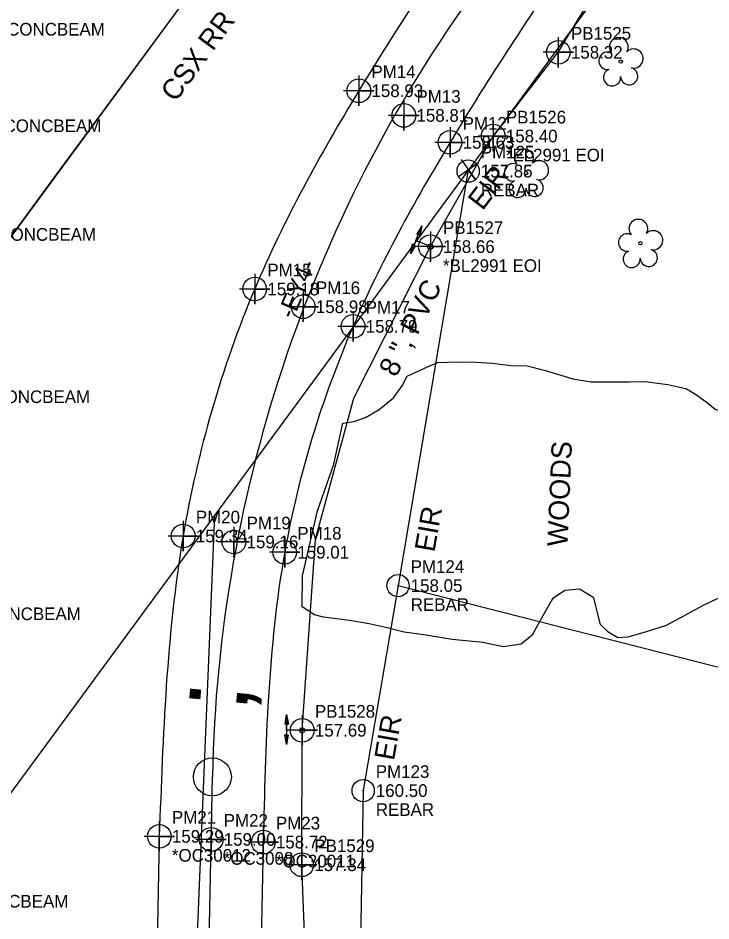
# Model space of a CAD drawing. Extents: x 2262665 to 2270527, y 505476 to 514960.
# Drawn here: x 2266364.6 to 2266501.5, y 510510.2 to 510688.6 of the extents above; entities that cross this region are included whole.
import ezdxf

# ---------------------------------------------------------------- set-up
doc = ezdxf.new("R2010")
doc.units = 0
for name, color, linetype in [('Default Symbol Cogo Comment', 7, 'Continuous'), ('Default Symbol Cogo Elevation', 7, 'Continuous'), ('Default Symbol Cogo Number', 7, 'Continuous'), ('Exist DTM Crownline Cogo Comment', 7, 'Continuous'), ('Exist DTM Crownline Cogo Elevation', 7, 'Continuous'), ('Exist DTM Crownline Cogo Number', 7, 'Continuous'), ('Exist DTM Crownline Cogo Point CELL', 7, 'Continuous'), ('Exist Horizontal Alignment', 7, 'Continuous'), ('Exist Horizontal Alignment Direction Label', 7, 'Continuous'), ('Exist Property Corner CELL', 7, 'Continuous'), ('Exist Property Iron Pin CELL', 7, 'Continuous'), ('Exist Property Iron Pin Cogo Comment', 7, 'Continuous'), ('Exist Property Iron Pin Cogo Elevation', 7, 'Continuous'), ('Exist Property Iron Pin Cogo Number', 7, 'Continuous'), ('Exist Property Iron Pin Text', 7, 'Continuous'), ('Exist Property Line', 7, 'Continuous'), ('Exist Railroads Standard Gauge', 7, 'Continuous'), ('Exist Railroads Standard Gauge Text', 7, 'Continuous'), ('Exist Right of Way Line', 7, 'Continuous'), ('Exist Roads EOP', 7, 'Continuous'), ('Exist Roads EOP Cogo Comment', 7, 'Continuous'), ('Exist Roads EOP Cogo Elevation', 7, 'Continuous'), ('Exist Roads EOP Cogo Number', 7, 'Continuous'), ('Exist Roads EOP Cogo Point CELL', 7, 'Continuous'), ('Exist Utilities Water Change of Service SUE CELL', 7, 'Continuous'), ('Exist Utilities Water UG Line SUE LOS B', 7, 'Continuous'), ('Exist Utilities Water UG Line SUE LOS B Cogo Comment', 7, 'Continuous'), ('Exist Utilities Water UG Line SUE LOS B Cogo Elevation', 7, 'Continuous'), ('Exist Utilities Water UG Line SUE LOS B Cogo Number', 7, 'Continuous'), ('Exist Utilities Water UG Line SUE LOS B Cogo Point CELL', 7, 'Continuous'), ('Exist Utilities Water UG Line SUE LOS B Text', 7, 'Continuous'), ('Exist Utilities Water UG Line SUE LOS C', 7, 'Continuous'), ('Exist Vegetation Tree CELL', 7, 'Continuous'), ('Exist Vegetation Woods Line', 7, 'Continuous'), ('Exist Vegetation Woods Line Text', 7, 'Continuous'), ('Scratch_Level_1', 7, 'Continuous')]:
    doc.layers.add(name, color=color, linetype=linetype)

msp = doc.modelspace()

# ---------------------------------------------------------------- linework, layer by layer
at = {"layer": 'Exist DTM Crownline Cogo Point CELL'}
for points in [[(2266440.82, 510672.39), (2266440.82, 510666.39), (2266440.82, 510669.39), (2266443.82, 510669.39), (2266437.82, 510669.39)], [(2266420.94, 510634.58), (2266420.94, 510628.58), (2266420.94, 510631.58), (2266423.94, 510631.58), (2266417.94, 510631.58)], [(2266407.24, 510588.1), (2266407.24, 510582.1), (2266407.24, 510585.1), (2266410.24, 510585.1), (2266404.24, 510585.1)], [(2266402.73, 510529.32), (2266402.73, 510523.32), (2266402.73, 510526.32), (2266405.73, 510526.32), (2266399.73, 510526.32)]]:
    msp.add_lwpolyline(points, dxfattribs=at)
for centre in [(2266440.82, 510669.39), (2266420.94, 510631.58), (2266407.24, 510585.1), (2266402.73, 510526.32)]:
    msp.add_circle(centre, 2.34, dxfattribs=at)
at = {"layer": 'Exist Horizontal Alignment'}
for p, q in [((2266115.37, 510308.34), (2266484.61, 510810.55)), ((2266397.92, 510285.5), (2266402.98, 510538.68))]:
    msp.add_line(p, q, dxfattribs=at)
msp.add_circle((2266402.98, 510538.68), 3.75, dxfattribs=at)
msp.add_arc((2266677.92, 510533.19), 275, 143.4649, 178.8564, dxfattribs=at)
at = {"layer": 'Exist Property Corner CELL'}
msp.add_line((2266453.57, 510658.61), (2266453.57, 510658.61), dxfattribs=at)
msp.add_lwpolyline([(2266452.13, 510660.65), (2266455.02, 510656.57), (2266453.57, 510658.61), (2266455.61, 510660.06), (2266451.54, 510657.16)], dxfattribs=at)
at = {"layer": 'Exist Property Iron Pin CELL'}
for centre, radius in [((2266453.54, 510658.38), 2.2), ((2266453.54, 510658.38), 0.0707), ((2266439.68, 510576.48), 2.2), ((2266439.68, 510576.48), 0.0707), ((2266432.78, 510535.97), 2.2), ((2266432.78, 510535.97), 0.0707)]:
    msp.add_circle(centre, radius, dxfattribs=at)
at = {"layer": 'Exist Property Line'}
msp.add_line((2266439.68, 510576.48), (2266650.69, 510522.69), dxfattribs=at)
at = {"layer": 'Exist Railroads Standard Gauge'}
msp.add_lwpolyline([(2266050.13, 510219.7), (2266084.79, 510266.49), (2266115.4, 510308.45), (2266145.35, 510349.15), (2266177.14, 510392.25), (2266205.29, 510430.68), (2266238.56, 510475.95), (2266285.01, 510539.01), (2266316.09, 510581.21), (2266370.93, 510656.02), (2266407.4, 510705.52), (2266453.51, 510768.36), (2266484.6, 510810.49), (2266484.6, 510810.49), (2266581.19, 510941.59), (2266616.47, 510989.01)], dxfattribs=at)
at = {"layer": 'Exist Right of Way Line'}
for p, q in [((2266927.92, 511303.77), (2265541.79, 509418.49)), ((2266453.57, 510658.61), (2266439.68, 510576.48)), ((2266439.68, 510576.48), (2266432.78, 510535.97)), ((2266432.78, 510535.97), (2266427.23, 510222.84))]:
    msp.add_line(p, q, dxfattribs=at)
at = {"layer": 'Exist Roads EOP'}
for points in [[(2266392.49, 510526.92), (2266390.63, 510426.97), (2266389.2, 510321.43), (2266387.02, 510213.77)], [(2266413.04, 510525.79), (2266411.05, 510426.91), (2266409.59, 510321.14), (2266405.94, 510212.74)]]:
    msp.add_lwpolyline(points, dxfattribs=at)
for points in [[(2266484.46, 510750.28), (2266457.74, 510713.54), (2266431.92, 510674.26), (2266411.35, 510635.08), (2266397.21, 510586.27), (2266392.49, 510526.92)], [(2266500.79, 510738.24), (2266474.62, 510701.96), (2266449.95, 510664.06), (2266430.79, 510627.7), (2266417.27, 510583.06), (2266413.04, 510525.79)]]:
    msp.add_spline(points, degree=3, dxfattribs=at)
at = {"layer": 'Exist Roads EOP Cogo Point CELL'}
for points in [[(2266431.92, 510677.26), (2266431.92, 510671.26), (2266431.92, 510674.26), (2266434.92, 510674.26), (2266428.92, 510674.26)], [(2266449.95, 510667.06), (2266449.95, 510661.06), (2266449.95, 510664.06), (2266452.95, 510664.06), (2266446.95, 510664.06)], [(2266411.35, 510638.08), (2266411.35, 510632.08), (2266411.35, 510635.08), (2266414.35, 510635.08), (2266408.35, 510635.08)], [(2266430.79, 510630.7), (2266430.79, 510624.7), (2266430.79, 510627.7), (2266433.79, 510627.7), (2266427.79, 510627.7)], [(2266397.21, 510589.27), (2266397.21, 510583.27), (2266397.21, 510586.27), (2266400.21, 510586.27), (2266394.21, 510586.27)], [(2266417.27, 510586.06), (2266417.27, 510580.06), (2266417.27, 510583.06), (2266420.27, 510583.06), (2266414.27, 510583.06)], [(2266392.49, 510529.92), (2266392.49, 510523.92), (2266392.49, 510526.92), (2266395.49, 510526.92), (2266389.49, 510526.92)], [(2266413.04, 510528.79), (2266413.04, 510522.79), (2266413.04, 510525.79), (2266416.04, 510525.79), (2266410.04, 510525.79)]]:
    msp.add_lwpolyline(points, dxfattribs=at)
for centre in [(2266431.92, 510674.26), (2266449.95, 510664.06), (2266411.35, 510635.08), (2266430.79, 510627.7), (2266397.21, 510586.27), (2266417.27, 510583.06), (2266392.49, 510526.92), (2266413.04, 510525.79)]:
    msp.add_circle(centre, 2.34, dxfattribs=at)
at = {"layer": 'Exist Utilities Water Change of Service SUE CELL'}
for p, q in [((2266444.41, 510647.54), (2266442.13, 510642.03)), ((2266443.21, 510644.64), (2266444.41, 510647.54)), ((2266446.06, 510643.46), (2266443.21, 510644.64)), ((2266446.06, 510643.46), (2266446.06, 510643.46)), ((2266417.65, 510547.88), (2266417.65, 510551.01)), ((2266417.65, 510551.01), (2266417.65, 510545.05)), ((2266420.74, 510547.88), (2266417.65, 510547.88)), ((2266420.74, 510547.88), (2266420.74, 510547.88))]:
    msp.add_line(p, q, dxfattribs=at)
for points in [[(2266444.41, 510647.54), (2266443.97, 510645.58), (2266443.81, 510646.1), (2266443.39, 510645.87)], [(2266442.13, 510642.03), (2266442.56, 510643.98), (2266442.72, 510643.46), (2266443.15, 510643.69)], [(2266417.65, 510551.01), (2266418, 510549.04), (2266417.65, 510549.46), (2266417.35, 510549.08)], [(2266417.65, 510545.05), (2266417.31, 510547.02), (2266417.65, 510546.6), (2266417.96, 510546.98)]]:
    msp.add_lwpolyline(points, close=True, dxfattribs=at)
for centre in [(2266446.06, 510643.46), (2266420.74, 510547.88)]:
    msp.add_circle(centre, 0.517, dxfattribs=at)
at = {"layer": 'Exist Utilities Water UG Line SUE LOS B'}
for points in [[(2266446.06, 510643.46), (2266458.49, 510665.31), (2266471.35, 510681.86), (2266483.55, 510701.95), (2266497.92, 510725), (2266508.62, 510741.88), (2266518.89, 510755), (2266527.04, 510765.25), (2266559.99, 510805.68), (2266579.75, 510830.86), (2266602.83, 510860.96), (2266626.07, 510891.4), (2266648.6, 510922.1), (2266650.64, 510924.83)], [(2266386.17, 509969.57), (2266389.96, 509994.37), (2266394.92, 510029.39), (2266399.7, 510068.24), (2266404.61, 510097.81), (2266408.39, 510129.36), (2266410.22, 510160.56), (2266410.6, 510188.7), (2266412.36, 510211.22), (2266417.15, 510247.49), (2266420.45, 510268.65), (2266421.2, 510321.49), (2266420.63, 510348.94), (2266421.94, 510381.57), (2266422.03, 510418.7), (2266422.43, 510454.93), (2266421.94, 510489.06), (2266420.64, 510521.31), (2266420.74, 510547.88)]]:
    msp.add_lwpolyline(points, dxfattribs=at)
at = {"layer": 'Exist Utilities Water UG Line SUE LOS B Cogo Point CELL'}
for points in [[(2266471.35, 510684.86), (2266471.35, 510678.86), (2266471.35, 510681.86), (2266474.35, 510681.86), (2266468.35, 510681.86)], [(2266458.49, 510668.31), (2266458.49, 510662.31), (2266458.49, 510665.31), (2266461.49, 510665.31), (2266455.49, 510665.31)], [(2266446.06, 510646.46), (2266446.06, 510640.46), (2266446.06, 510643.46), (2266449.06, 510643.46), (2266443.06, 510643.46)], [(2266420.74, 510550.88), (2266420.74, 510544.88), (2266420.74, 510547.88), (2266423.74, 510547.88), (2266417.74, 510547.88)], [(2266420.64, 510524.31), (2266420.64, 510518.31), (2266420.64, 510521.31), (2266423.64, 510521.31), (2266417.64, 510521.31)]]:
    msp.add_lwpolyline(points, dxfattribs=at)
for centre in [(2266471.35, 510681.86), (2266458.49, 510665.31), (2266446.06, 510643.46), (2266420.74, 510547.88), (2266420.64, 510521.31)]:
    msp.add_circle(centre, 2.34, dxfattribs=at)
at = {"layer": 'Exist Utilities Water UG Line SUE LOS C'}
for points in [[(2266430.93, 510613.52), (2266446.06, 510643.46)], [(2266420.74, 510547.88), (2266423.33, 510585.68), (2266430.93, 510613.52)]]:
    msp.add_lwpolyline(points, dxfattribs=at)
at = {"layer": 'Exist Vegetation Tree CELL'}
for p, q in [((2266483.7, 510680.03), (2266483.7, 510680.03)), ((2266465, 510657.98), (2266465, 510657.98)), ((2266487.57, 510644.13), (2266487.57, 510644.13))]:
    msp.add_line(p, q, dxfattribs=at)
for centre in [(2266483.7, 510680.03), (2266465, 510657.98), (2266487.57, 510644.13)]:
    msp.add_circle(centre, 0.326, dxfattribs=at)
for centre, radius, start, end in [((2266483.31, 510682.9), 1.86, 330.1651, 219.7134), ((2266481.09, 510680.18), 1.73, 62.6636, 279.3457), ((2266486.24, 510680.62), 1.9, 257.1011, 134.1999), ((2266481.99, 510676.91), 1.69, 111.5671, 6.231), ((2266485.37, 510677.13), 1.7, 181.2822, 74.56), ((2266464.62, 510660.86), 1.86, 330.1651, 219.7134), ((2266467.55, 510658.57), 1.9, 257.1011, 134.1999), ((2266462.4, 510658.14), 1.73, 62.6636, 279.3457), ((2266466.68, 510655.08), 1.7, 181.2822, 74.56), ((2266463.3, 510654.86), 1.69, 111.5671, 6.231), ((2266487.18, 510647), 1.86, 330.1651, 219.7134), ((2266484.96, 510644.28), 1.73, 62.6636, 279.3457), ((2266490.12, 510644.72), 1.9, 257.1011, 134.1999), ((2266485.86, 510641.01), 1.69, 111.5671, 6.231), ((2266489.24, 510641.23), 1.7, 181.2822, 74.56)]:
    msp.add_arc(centre, radius, start, end, dxfattribs=at)
at = {"layer": 'Exist Vegetation Woods Line'}
msp.add_line((2266455.09, 510620.6), (2266458.26, 510620.42), dxfattribs=at)
for points in [[(2266423.75, 510591.27), (2266426.99, 510600.44), (2266428.79, 510608.6), (2266430.91, 510608.89), (2266433.23, 510609.69), (2266435.93, 510611.28), (2266438.8, 510613.56), (2266440.52, 510615.95), (2266441.48, 510617.88), (2266444.89, 510619.47), (2266447.5, 510620.58), (2266451.45, 510620.7), (2266455.09, 510620.6)], [(2266458.26, 510620.42), (2266461.94, 510619.99), (2266465.2, 510619.92), (2266468.57, 510619.08), (2266471.84, 510618.03), (2266474.21, 510617.32), (2266477.82, 510616.72), (2266482.17, 510616.73), (2266485.43, 510616.73), (2266488.47, 510616.79), (2266493.02, 510616.21), (2266496.54, 510615.4), (2266498.47, 510614.32), (2266500.61, 510612.81), (2266502.39, 510611.34), (2266505.25, 510610.36), (2266508.47, 510610.29), (2266510.97, 510611.37), (2266514.87, 510612.24), (2266516.73, 510612.56)], [(2266424.93, 510570.23), (2266423.18, 510570.73), (2266420.7, 510572.27), (2266420.78, 510578.39), (2266423.75, 510591.27)], [(2266503.01, 510573.97), (2266499.96, 510572.57), (2266495.22, 510569.97), (2266492.69, 510568.56), (2266488.72, 510567.32), (2266485.07, 510566.31), (2266483.14, 510566.18), (2266481.33, 510567.18), (2266479.68, 510568.79), (2266479.19, 510570.82), (2266478.37, 510574.04), (2266475.57, 510575.76), (2266472.66, 510575.51), (2266470.18, 510573.83), (2266467.76, 510569.59), (2266466.18, 510566.67), (2266464, 510564.89), (2266460.47, 510564.39), (2266456.46, 510565.25), (2266450.37, 510565.81), (2266445.24, 510566.66), (2266440.92, 510567.29), (2266437.55, 510568.16), (2266433.99, 510568.94), (2266430.11, 510569.56), (2266424.93, 510570.23)]]:
    msp.add_lwpolyline(points, dxfattribs=at)
at = {"layer": 'Scratch_Level_1'}
for p, q in [((2266392.99, 510337.11), (2266403.46, 510590.45)), ((2266402.92, 510559.46), (2266402.92, 510559.46))]:
    msp.add_line(p, q, dxfattribs=at)

# ---------------------------------------------------------------- texts
at = {"layer": 'Default Symbol Cogo Comment'}
for p in [(2266348.11, 510685.17), (2266347.41, 510666.09), (2266346.38, 510644.62), (2266345.2, 510612.55), (2266343.36, 510569.65), (2266340.9, 510512.85)]:
    msp.add_text('BOTTOMCONCBEAM', height=2.5, dxfattribs=at).set_placement(p)
at = {"layer": 'Default Symbol Cogo Elevation'}
msp.add_text('158.05', height=2.5, dxfattribs=at).set_placement((2266442.18, 510575.23))
at = {"layer": 'Default Symbol Cogo Number'}
msp.add_text('PM124', height=2.5, dxfattribs=at).set_placement((2266442.18, 510578.98))
at = {"layer": 'Exist DTM Crownline Cogo Comment'}
msp.add_text('*OC3008', height=2.5, dxfattribs=at).set_placement((2266405.23, 510521.32))
at = {"layer": 'Exist DTM Crownline Cogo Elevation'}
for s, p in [('158.81', (2266443.32, 510668.14)), ('158.98', (2266423.44, 510630.33)), ('159.16', (2266409.74, 510583.85)), ('159.00', (2266405.23, 510525.07))]:
    msp.add_text(s, height=2.5, dxfattribs=at).set_placement(p)
at = {"layer": 'Exist DTM Crownline Cogo Number'}
for s, p in [('PM13', (2266443.32, 510671.89)), ('PM16', (2266423.44, 510634.08)), ('PM19', (2266409.74, 510587.6)), ('PM22', (2266405.23, 510528.82))]:
    msp.add_text(s, height=2.5, dxfattribs=at).set_placement(p)
at = {"layer": 'Exist Horizontal Alignment Direction Label'}
msp.add_text('-EY4-', height=3.5, rotation=67.3222, dxfattribs=at).set_placement((2266418.98, 510628.96))
at = {"layer": 'Exist Property Iron Pin Cogo Comment'}
for p in [(2266456.04, 510653.38), (2266442.18, 510571.48), (2266435.28, 510530.97)]:
    msp.add_text('REBAR', height=2.5, dxfattribs=at).set_placement(p)
at = {"layer": 'Exist Property Iron Pin Cogo Elevation'}
for s, p in [('157.85', (2266456.04, 510657.13)), ('158.05', (2266442.18, 510575.23)), ('160.50', (2266435.28, 510534.72))]:
    msp.add_text(s, height=2.5, dxfattribs=at).set_placement(p)
at = {"layer": 'Exist Property Iron Pin Cogo Number'}
for s, p in [('PM125', (2266456.04, 510660.88)), ('PM124', (2266442.18, 510578.98)), ('PM123', (2266435.28, 510538.47))]:
    msp.add_text(s, height=2.5, dxfattribs=at).set_placement(p)
at = {"layer": 'Exist Property Iron Pin Text'}
for rotation, p in [(52.547, (2266456.36, 510650.44)), (80.0001, (2266446.86, 510582.95)), (80.0001, (2266438.88, 510541.76)), (80.0001, (2266438.88, 510541.76))]:
    msp.add_text('EIR', height=4, rotation=rotation, dxfattribs=at).set_placement(p)
at = {"layer": 'Exist Railroads Standard Gauge Text'}
msp.add_text('CSX RR', height=4, rotation=53.7747, dxfattribs=at).set_placement((2266395.7, 510671.86))
at = {"layer": 'Exist Roads EOP Cogo Comment'}
for s, p in [('*OC30012', (2266394.99, 510521.92)), ('*OC30011', (2266415.54, 510520.79))]:
    msp.add_text(s, height=2.5, dxfattribs=at).set_placement(p)
at = {"layer": 'Exist Roads EOP Cogo Elevation'}
for s, p in [('158.93', (2266434.42, 510673.01)), ('158.63', (2266452.45, 510662.81)), ('159.18', (2266413.85, 510633.83)), ('158.79', (2266433.29, 510626.45)), ('159.34', (2266399.71, 510585.02)), ('159.01', (2266419.77, 510581.81)), ('159.29', (2266394.99, 510525.67)), ('158.72', (2266415.54, 510524.54))]:
    msp.add_text(s, height=2.5, dxfattribs=at).set_placement(p)
at = {"layer": 'Exist Roads EOP Cogo Number'}
for s, p in [('PM14', (2266434.42, 510676.76)), ('PM12', (2266452.45, 510666.56)), ('PM15', (2266413.85, 510637.58)), ('PM17', (2266433.29, 510630.2)), ('PM20', (2266399.71, 510588.77)), ('PM18', (2266419.77, 510585.56)), ('PM21', (2266394.99, 510529.42)), ('PM23', (2266415.54, 510528.29))]:
    msp.add_text(s, height=2.5, dxfattribs=at).set_placement(p)
at = {"layer": 'Exist Utilities Water UG Line SUE LOS B Cogo Comment'}
for s, p in [('*EL2991 EOI', (2266460.99, 510660.31)), ('*BL2991 EOI', (2266448.56, 510638.46))]:
    msp.add_text(s, height=2.5, dxfattribs=at).set_placement(p)
at = {"layer": 'Exist Utilities Water UG Line SUE LOS B Cogo Elevation'}
for s, p in [('158.32', (2266473.85, 510680.61)), ('158.40', (2266460.99, 510664.06)), ('158.66', (2266448.56, 510642.21)), ('157.69', (2266423.24, 510546.63)), ('157.34', (2266423.14, 510520.06))]:
    msp.add_text(s, height=2.5, dxfattribs=at).set_placement(p)
at = {"layer": 'Exist Utilities Water UG Line SUE LOS B Cogo Number'}
for s, p in [('PB1525', (2266473.85, 510684.36)), ('PB1526', (2266460.99, 510667.81)), ('PB1527', (2266448.56, 510645.96)), ('PB1528', (2266423.24, 510550.38)), ('PB1529', (2266423.14, 510523.81))]:
    msp.add_text(s, height=2.5, dxfattribs=at).set_placement(p)
at = {"layer": 'Exist Utilities Water UG Line SUE LOS B Text'}
msp.add_text('8 ", PVC', height=4, rotation=63.1966, dxfattribs=at).set_placement((2266439.28, 510617.48))
at = {"layer": 'Exist Vegetation Woods Line Text'}
msp.add_text('WOODS', height=4, rotation=87.4803, dxfattribs=at).set_placement((2266473.15, 510584.14))
at = {"layer": 'Scratch_Level_1'}
msp.add_text(';', height=15, rotation=84.8045, dxfattribs=at).set_placement((2266409.71, 510551.32))

doc.saveas('drawing.dxf')
